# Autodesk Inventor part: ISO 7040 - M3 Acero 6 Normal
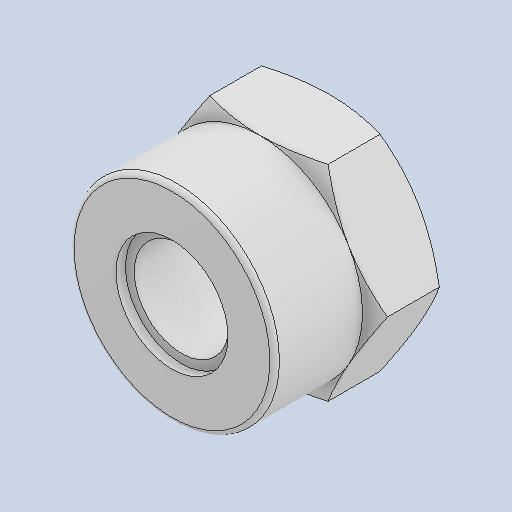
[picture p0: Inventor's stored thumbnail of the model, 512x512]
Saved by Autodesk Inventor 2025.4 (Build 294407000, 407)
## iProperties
Created: 2026-09
Part Number: ISO 7040 - M3 Acero 6 Normal
Material: Generic
Description: Tuerca autoblocante hexagonal normal ISO 7040 - M3
Document SubType Name: Modeling
Designer: AdminForWorker
Density: 1 g/cm^3
Appearance: Default
Title: Tuerca autoblocante hexagonal normal ISO 7040 - M3 Acero 6 Normal v1
Author: AdminForWorker
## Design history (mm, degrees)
feature "Body5"
feature "Body6"
body "Solid1"
body "Solid2"
